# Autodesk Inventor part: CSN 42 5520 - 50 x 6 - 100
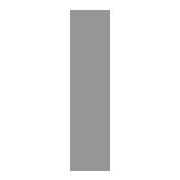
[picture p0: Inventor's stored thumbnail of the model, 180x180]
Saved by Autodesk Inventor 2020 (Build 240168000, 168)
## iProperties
IsCustomPart: 1
Created: 2019-01
Part Number: CSN 42 5520 - 50 x 6 - 100
Material: Ocel
Description: Tyč
Document SubType Name: Modeling
Standard: CSN 42 5520
Designer: doma
Standards Organization: CSN
Language: cs-CZ
Size Designation: 50 x 6 - 100
Categories: <MemberInstance><Categories><Category DisplayName="Konstrukční profily" InternalName="089c4875-fa83-4c05-b084-43b9cc11f5ed" Mnemonic="GRDR"><CategoryParameter D
Stock Number: 50 x 6
Density: 7.85 g/cm^3
Appearance: Plech
Mass: 85.7842 g
Surface Area: 46.7976 cm^2
Volume: 10.9279 cm^3
G_L: 100,000 mm
Author: doma
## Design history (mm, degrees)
node "Počáteční rovina"
node "Koncová rovina"
sketch "Náčrt"
  geometry: L1 (3, -25)-(-3, -25); L2 (-3, -25)-(-3, 25); L3 (-3, 25)-(3, 25); L4 (3, 25)-(3, -25); L5 (-6, 0)-(8, 0); L6 (0, -30)-(0, 40); L7 (0, 54)-(0, -44) reference; L8 (-9.2, 0)-(13.2, 0) reference
  constraints: 12 end point, 2 collinear, 2 parallel, 1 horizontal, 1 perpendicular
  dimensions: "d0" = 50 distance between parallel lines of L3 L1 (= G_W); "d1" = 6 distance between parallel lines of L4 L2 (= G_H); "d4" = 3 distance between parallel lines of L6 L4 (= 0.5 x d1); "d5" = 25 distance between parallel lines of L5 L3 (= 0.5 x d0)
extrude "Těleso" new body sketch "Náčrt" stored distance "d2" = 100 (= G_L); taper "d3" = 0 deg
node "Driven Length"
  sketch "Sketch3"
    geometry: L1 (0, 0)-(10, 0) reference
    constraints: 2 end point, 1 horizontal
  workplane "Work Plane3"
  sketch "Sketch4"
    geometry: L1 (-2, 0)-(12, 0) reference; L2 (-2, 100)-(12, 100) reference
    dimensions: "d9" = 100 distance between parallel lines of L1 L2 (derived)
sketch "Náčrt5"
  geometry: L1 (7.644, 57.574)-(10.321, -19.845); L2 (10.321, -19.845)-(-18.229, -26.09); L3 (-18.229, -26.09)-(-31.018, 60.453); L4 (0, 63.574)-(-6, 63.574); L5 (-6, 63.574)-(-31.018, 60.453); L6 (0, 63.574)-(7.644, 57.574); 1 further point
  constraints: 12 end point, 1 horizontal
extrude "Vysunutí2" cut sketch "Náčrt5" extent not by distance; stored distance "d10" = 0; taper "d11" = 0 deg
body "Solid1"
other parameters: "G_W" = 50 [user parameter; used in 1 equation term], "G_H" = 6 [user parameter; used in 1 equation term], "G_L" = 100 (= d9) [user parameter; used in 1 equation term], "G_OFFSET_START" = 0 [user parameter; used in 1 equation term], "G_OFFSET_END" = 0 [user parameter; used in 1 equation term], "d6" = 0 (computed from G_OFFSET_START), "d8" = 90 deg
